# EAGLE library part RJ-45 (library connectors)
AMP connector Digikey part number: A9033-ND
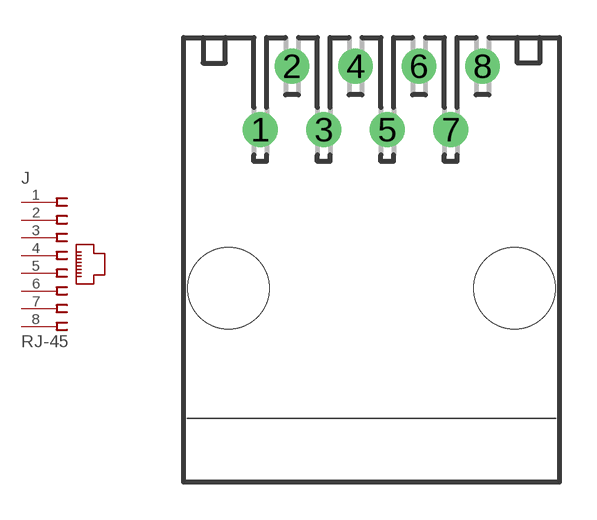
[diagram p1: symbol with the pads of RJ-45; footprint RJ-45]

Designator prefix J

## RJ-45-TH  [RJ-45]
1  1  pas
2  2  pas
3  3  pas
4  4  pas
5  5  pas
6  6  pas
7  7  pas
8  8  pas

## Footprint RJ-45 (pad centres in mm)
Modular Jack without Panel Stops
drill 0.889 round: 1 -4.445,5.207; 2 -3.175,7.747; 3 -1.905,5.207; 4 -0.635,7.747; 5 0.635,5.207; 6 1.905,7.747; 7 3.175,5.207; 8 4.445,7.747
hole 3.251 at -5.715,-1.143
hole 3.251 at 5.715,-1.143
